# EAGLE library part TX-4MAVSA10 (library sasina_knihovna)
Vysilaci modul pro 433 MHz.
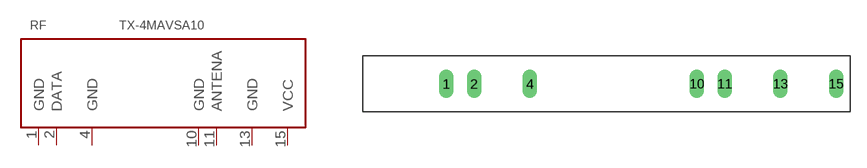
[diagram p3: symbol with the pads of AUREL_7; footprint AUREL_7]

Designator prefix RF

## TX-4MAVSA10  [AUREL_7]
1  GND  sup
2  DATA  in
4  GND  sup
10  GND  sup
11  ANTENA  out
13  GND  sup
15  VCC  sup

## Footprint AUREL_7 (pad centres in mm)
drill 0.8 long: 1 -10.16,2.54; 2 -7.62,2.54; 4 -2.54,2.54; 10 12.7,2.54; 11 15.24,2.54; 13 20.32,2.54; 15 25.4,2.54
